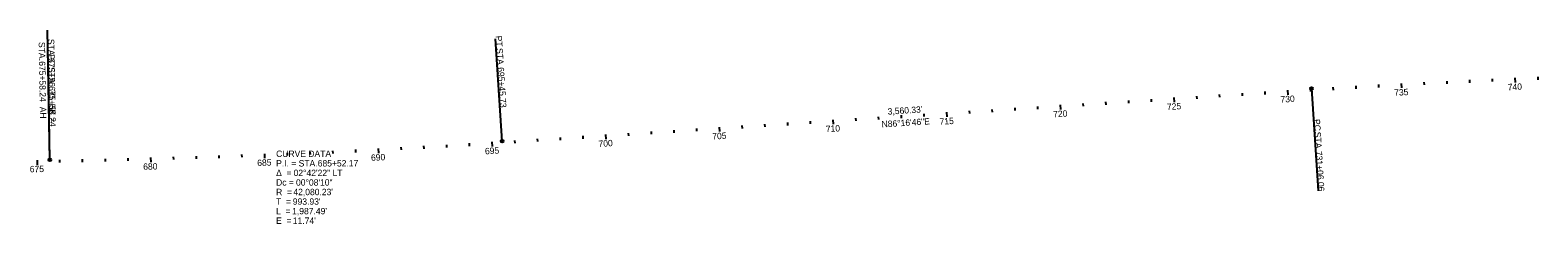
# Model space of a CAD drawing. Extents: x 117326 to 225548, y 573011 to 581051.
# Drawn here: x 184929 to 191547, y 577481 to 578331 of the extents above; entities that cross this region are included whole.
import ezdxf

# ---------------------------------------------------------------- set-up
doc = ezdxf.new("R2010")
doc.units = 0
for name, color, linetype in [('_CIVIL_CONSTRUCTION', 7, 'Continuous'), ('GE_P_Alignment', 7, 'Continuous'), ('GE_P_Alignment_100_Bearings', 7, 'Continuous'), ('GE_P_Alignment_100_Cardinal_Points', 7, 'Continuous'), ('GE_P_Alignment_100_Curve_Data', 7, 'Continuous')]:
    doc.layers.add(name, color=color, linetype=linetype)

msp = doc.modelspace()

# ---------------------------------------------------------------- linework, layer by layer
at = {"layer": 'GE_P_Alignment'}
for p, q in [((185015.9, 577761.6), (185005.8, 578331.5)), ((187001.5, 577843.7), (186972.3, 578292.7)), ((185015.9, 577761.6), (185007.9, 578211.5)), ((190554.3, 578074.7), (190582.4, 577625.6))]:
    msp.add_line(p, q, dxfattribs=at)
for centre in [(190554.3, 578074.7), (187001.5, 577843.7), (185015.9, 577761.6), (185015.9, 577761.6)]:
    msp.add_circle(centre, 6, dxfattribs=at)
at = {"layer": 'GE_P_Alignment_100_Curve_Data'}
for p, q in [((191347.1, 578117.2), (191347.6, 578105.2)), ((191447, 578121.6), (191447.9, 578101.6)), ((191546.9, 578125.7), (191547.4, 578113.7)), ((190248.9, 578054.8), (190249.7, 578042.9)), ((190348.7, 578061.3), (190349.5, 578049.4)), ((190448.5, 578067.8), (190449.8, 578047.9)), ((190548.3, 578074.3), (190549, 578062.3)), ((190648.1, 578080.5), (190648.8, 578068.5)), ((190747.9, 578086.4), (190748.6, 578074.4)), ((190847.7, 578092.1), (190848.4, 578080.1)), ((190947.6, 578097.6), (190948.7, 578077.6)), ((191047.4, 578102.8), (191048.1, 578090.8)), ((191147.3, 578107.8), (191147.9, 578095.9)), ((191247.2, 578112.6), (191247.8, 578100.7)), ((189251, 577989.9), (189251.8, 577978)), ((189350.8, 577996.4), (189351.6, 577984.5)), ((189450.6, 578002.9), (189451.9, 577983)), ((189550.4, 578009.4), (189551.1, 577997.4)), ((189650.2, 578015.9), (189650.9, 578003.9)), ((189749.9, 578022.4), (189750.7, 578010.4)), ((189849.7, 578028.9), (189850.5, 578016.9)), ((189949.5, 578035.4), (189950.8, 578015.4)), ((190049.3, 578041.9), (190050.1, 578029.9)), ((190149.1, 578048.3), (190149.9, 578036.4)), ((188153.3, 577918.6), (188154.1, 577906.6)), ((188253.1, 577925.1), (188253.9, 577913.1)), ((188352.9, 577931.5), (188353.7, 577919.6)), ((188452.7, 577938), (188454, 577918.1)), ((188552.5, 577944.5), (188553.3, 577932.5)), ((188652.3, 577951), (188653, 577939)), ((188752.1, 577957.5), (188752.8, 577945.5)), ((188851.8, 577964), (188852.6, 577952)), ((188951.6, 577970.5), (188952.9, 577950.5)), ((189051.4, 577977), (189052.2, 577965)), ((189151.2, 577983.5), (189152, 577971.5)), ((187155.4, 577853.7), (187156.2, 577841.7)), ((187255.2, 577860.2), (187256, 577848.2)), ((187355, 577866.7), (187355.8, 577854.7)), ((187454.8, 577873.1), (187456.1, 577853.2)), ((187554.6, 577879.6), (187555.4, 577867.7)), ((187654.4, 577886.1), (187655.2, 577874.1)), ((187754.2, 577892.6), (187754.9, 577880.6)), ((187854, 577899.1), (187854.7, 577887.1)), ((187953.7, 577905.6), (187955, 577885.6)), ((188053.5, 577912.1), (188054.3, 577900.1)), ((185957.2, 577788.8), (185958, 577768.8)), ((186057.1, 577792.9), (186057.6, 577780.9)), ((186157, 577797.3), (186157.6, 577785.3)), ((186256.9, 577801.9), (186257.5, 577789.9)), ((186356.8, 577806.7), (186357.4, 577794.7)), ((186456.7, 577811.8), (186457.7, 577791.8)), ((186556.5, 577817.1), (186557.2, 577805.1)), ((186656.4, 577822.6), (186657.1, 577810.7)), ((186756.2, 577828.4), (186756.9, 577816.5)), ((186856, 577834.5), (186856.8, 577822.5)), ((186955.8, 577840.7), (186957.1, 577820.8)), ((187055.6, 577847.2), (187056.4, 577835.2)), ((184959.6, 577760.6), (184959.9, 577740.6)), ((185057.6, 577762.3), (185057.9, 577750.3)), ((185157.6, 577764.3), (185157.9, 577752.3)), ((185257.6, 577766.5), (185257.9, 577754.5)), ((185357.6, 577769), (185357.9, 577757)), ((185457.5, 577771.7), (185458.1, 577751.7)), ((185557.5, 577774.6), (185557.8, 577762.7)), ((185657.4, 577777.8), (185657.8, 577765.8)), ((185757.4, 577781.2), (185757.8, 577769.2)), ((185857.3, 577784.9), (185857.8, 577772.9))]:
    msp.add_line(p, q, dxfattribs=at)

# ---------------------------------------------------------------- texts
at = {"layer": '_CIVIL_CONSTRUCTION'}
msp.add_text('N86°16\'46"E', height=28, rotation=3.72061, dxfattribs=at).set_placement((188667.6, 577903.9))
at = {"layer": 'GE_P_Alignment'}
for s, rotation, p in [('STA. ', 271.01448, (184966.2, 578279.2)), ('STA. ', 271.01448, (185006.9, 578292.6)), ('PT', 273.72061, (186971.8, 578306)), (' STA. ', 273.72061, (186974.7, 578262)), ('675+58.24', 271.01448, (184967.7, 578194.7)), ('PC', 271.01448, (185008.1, 578225.7)), ('675+56.30', 271.01448, (185008.4, 578208.1)), (' STA. ', 271.01448, (185008.9, 578179.8)), ('695+45.73', 273.72061, (186980.8, 578167.7)), ('675+58.24', 271.01448, (185010.6, 578085.3)), (' AH', 271.01448, (184971.1, 578005.1)), (' BK =', 271.01448, (185011.7, 578018.6)), ('PC', 273.57741, (190563.2, 577940)), (' STA. ', 273.57741, (190566, 577894.3)), ('731+06.06', 273.57741, (190571.9, 577799.9))]:
    msp.add_text(s, height=28, rotation=rotation, dxfattribs=at).set_placement(p)
at = {"layer": 'GE_P_Alignment_100_Bearings'}
for s, p in [('CURVE DATA', (186008.7, 577774.6)), ('P.I. = STA. ', (186008.7, 577732.6)), ('02°42\'22" LT', (186085.5, 577690.6)), ('685+52.17', (186191.4, 577732.6)), ('Δ  = ', (186008.7, 577690.6)), ('Dc = ', (186008.7, 577648.6)), ('00°08\'10"', (186096.1, 577648.6)), ('T  = ', (186008.7, 577564.6)), ('R  = ', (186008.7, 577606.6)), ("993.93'", (186082.1, 577564.6)), ("42,080.23'", (186084.5, 577606.6)), ('L  = ', (186008.7, 577522.6)), ("1,987.49'", (186079.1, 577522.6)), ('E  = ', (186008.7, 577480.6)), ("11.74'", (186082.1, 577480.6))]:
    msp.add_text(s, height=28, dxfattribs=at).set_placement(p)
at = {"layer": 'GE_P_Alignment_100_Cardinal_Points'}
msp.add_text("3,560.33'", height=28, rotation=3.72061, dxfattribs=at).set_placement((188694.2, 577960))
at = {"layer": 'GE_P_Alignment_100_Curve_Data'}
for s, rotation, p in [('735', 3.07464, (190917.4, 578042.9)), ('740', 2.4365, (191415.8, 578067.2)), ('725', 3.72061, (189920, 577980.3)), ('730', 3.72061, (190418.5, 578012.8)), ('715', 3.72061, (188922.1, 577915.4)), ('720', 3.72061, (189420.6, 577947.9)), ('705', 3.72061, (187924.2, 577850.6)), ('710', 3.72061, (188422.7, 577883)), ('690', 2.97755, (186426, 577757.1)), ('695', 3.65834, (186926.3, 577785.7)), ('700', 3.72061, (187424.8, 577818.1)), ('675', 1.01448, (184927.5, 577707)), ('680', 1.61597, (185425.6, 577717.8)), ('685', 2.29676, (185926.3, 577734.5))]:
    msp.add_text(s, height=28, rotation=rotation, dxfattribs=at).set_placement(p)

doc.saveas('drawing.dxf')
